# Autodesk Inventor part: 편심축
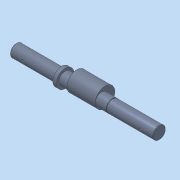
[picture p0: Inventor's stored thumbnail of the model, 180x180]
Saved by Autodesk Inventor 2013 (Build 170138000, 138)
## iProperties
Manager: 한국ATC센터
Company: 한국ATC센터
Created: 2014-10
Part Number: 편심축
Document SubType Name: Modeling
Designer: 한국ATC센터
Density: 7.86 g/cm^3
Material: 강, 연강
Mass: 1140.06 g
Surface Area: 226.679 cm^2
Volume: 145.046 cm^3
Author: KYOUNG IL JANG
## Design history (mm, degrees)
sketch "스케치1"
  geometry: L1 (-142, 0)-(142, 0); L2 (-142, 0)-(-142, 12.5); L3 (-142, 12.5)-(-52, 12.5); L4 (-52, 12.5)-(-52, 17.5); L5 (-52, 17.5)-(-45, 17.5); L6 (-45, 17.5)-(-45, 12.5); L7 (-45, 12.5)-(48.65, 12.5); L8 (48.65, 12.5)-(48.65, 11.95); L9 (48.65, 11.95)-(50, 11.95); L10 (50, 11.95)-(50, 12.5); L11 (50, 12.5)-(142, 12.5); L12 (142, 12.5)-(142, 0); L13 (109, 12.5)-(109, 9.1); L14 (109, 9.1)-(134, 9.1); L15 (134, 9.1)-(134, 12.5); L16 (117, -12.5)-(119.5, -12.5); L17 (119.5, -12.5)-(117, -10); L18 (117, -10)-(117, -12.5); L19 (-109, 12.5)-(-109, 9.1); L20 (-109, 9.1)-(-134, 9.1); L21 (-134, 9.1)-(-134, 12.5); L22 (-117, -12.5)-(-117, -10); L23 (-117, -10)-(-114.5, -12.5); L24 (-114.5, -12.5)-(-117, -12.5); 2 further points
  constraints: 48 end point, 11 parallel, 8 perpendicular, 5 collinear, 4 point on line, 1 coincident, 1 horizontal, 1 midpoint, 1 vertical
  dimensions: "d0" = 284 distance of L1.start L1.end (derived); "d1" = 25 diameter of L3 L1; "d2" = 35 diameter of L5 L1; "d3" = 90 distance of L2.end L3.end; "d4" = 187 distance between parallel lines of L12 L6; "d6" = 1.35 distance of L8.end L9.end; "d7" = 23.9 diameter of L9 L1; "d8" = 3.4 distance between parallel lines of L14 L11; "d9" = 8 distance between parallel lines of L15 L12; "d10" = 25 distance of L13.end L14.end; "d11" = 25 diameter of L16 L1 (= d1); "d12" = 25 distance from line of L12 L16.start; "d13" = 45 deg angle of L17 L18; "d14" = 5 diameter of L16.end L18; "d27" = 92 distance between parallel lines of L10 L12; "d32" = 7 distance of L4.end L5.end; "d33" = 8 distance between parallel lines of L2 L21; "d34" = 25 distance between parallel lines of L21 L19; "d35" = 3.4 distance between parallel lines of L3 L20; "d36" = 25 distance from line of L22.start L2; "d37" = 5 diameter of L23.end L22
revolve "회전1" stored, may be unused: angle "d15" = 90 deg
revolve "회전2" stored, may be unused: angle "d16" = 90 deg
revolve "회전3" stored, may be unused: angle "d38" = 90 deg
extrude "돌출1" cut sketch "스케치1" stored distance "d17" = 8; taper "d18" = 0 deg
fillet "모깎기1" dims "d19" = 4
node "작업 평면1"
sketch "스케치2"
  geometry: L1 (12.99, -6.5)-(8.66, -14); L2 (-12.99, -6.5)-(-8.66, -14); C1 r 12.5 at (0, 0) reference; C2 r 19.5 at (0, 7); A1 r 15 centre (0, 1) between (12.99, -6.5) and (-12.99, -6.5); A2 r 10 centre (0, -9) between (-8.66, -14) and (8.66, -14); 1 further point
  constraints: 5 tangent, 4 end point, 4 point on circle, 3 centre point, 3 vertical alignment
  dimensions: "d21" = 7 distance of point (0, 0) C2.centre; "d30" = 39 diameter of C2 (derived); "d39" = 10 distance of A2.centre A1.centre; "d40" = 30 diameter of A1; "d41" = 20 diameter of A2; "d42" = 1 distance of point (0, 0) A1.centre
extrude "돌출2" join sketch "스케치2" distance "d22" = 56; taper "d23" = 0 deg
chamfer "모따기1" distance "d24" = 1; stored, may be unused: second distance "d25" = 2, angle "d26" = 45 deg
node "솔리드1"
other parameters: "d20" = 16
